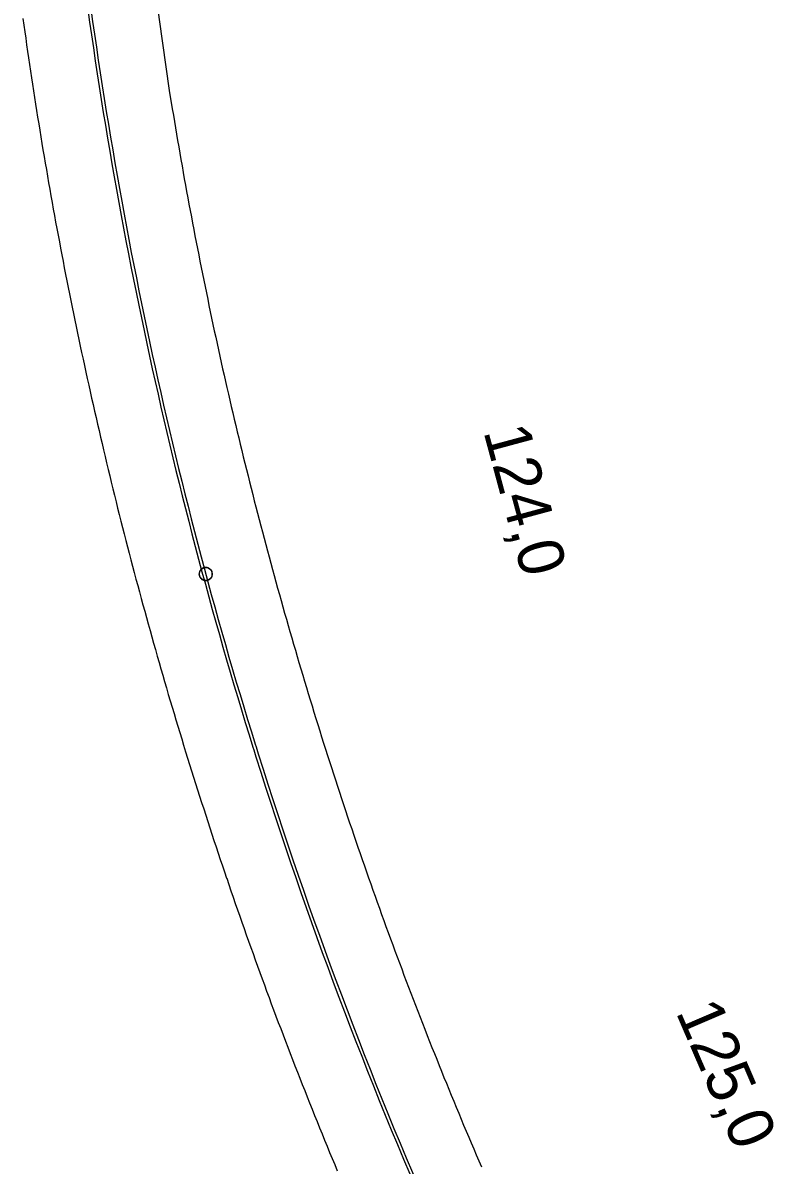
# Model space of a CAD drawing. Extents: x -670810 to -649614, y -1131928 to -1115069.
# Drawn here: x -670743 to -669596, y -1120256 to -1118513 of the extents above; entities that cross this region are included whole.
import ezdxf

# ---------------------------------------------------------------- set-up
doc = ezdxf.new("R2010")
doc.units = 0
for name, color, linetype in [('hranice_VRT_ZUR_Vysocina', 7, 'Continuous'), ('Situace - Osa koleje 2D', 7, 'Continuous'), ('Situace - Osa koleje tunel 2D', 7, 'Continuous'), ('Staničení - hlavní staničení + kolečka 1k', 7, 'Continuous')]:
    doc.layers.add(name, color=color, linetype=linetype)

# ---------------------------------------------------------------- blocks, each defined once
blk = doc.blocks.new('Sit10Kruh_101')
at = {"layer": 'Staničení - hlavní staničení + kolečka 1k'}
blk.add_lwpolyline([(10, 0), (9.98026, 0.6279), (9.92114, 1.25334), (9.82288, 1.87382), (9.68584, 2.4869), (9.51056, 3.09016), (9.29776, 3.68124), (9.04828, 4.2578), (8.76306, 4.81754), (8.44328, 5.35826), (8.09016, 5.87786), (7.70514, 6.37424), (7.28968, 6.84548), (6.84548, 7.28968), (6.37424, 7.70514), (5.87786, 8.09016), (5.35826, 8.44328), (4.81754, 8.76306), (4.2578, 9.04828), (3.68124, 9.29776), (3.09016, 9.51056), (2.4869, 9.68584), (1.87382, 9.82288), (1.25334, 9.92114), (0.6279, 9.98026), (0, 10), (-0.6279, 9.98026), (-1.25334, 9.92114), (-1.87382, 9.82288), (-2.4869, 9.68584), (-3.09016, 9.51056), (-3.68124, 9.29776), (-4.2578, 9.04828), (-4.81754, 8.76306), (-5.35826, 8.44328), (-5.87786, 8.09016), (-6.37424, 7.70514), (-6.84548, 7.28968), (-7.28968, 6.84548), (-7.70514, 6.37424), (-8.09016, 5.87786), (-8.44328, 5.35826), (-8.76306, 4.81754), (-9.04828, 4.2578), (-9.29776, 3.68124), (-9.51056, 3.09016), (-9.68584, 2.4869), (-9.82288, 1.87382), (-9.92114, 1.25334), (-9.98026, 0.6279), (-10, 0), (-9.98026, -0.6279), (-9.92114, -1.25334), (-9.82288, -1.87382), (-9.68584, -2.4869), (-9.51056, -3.09016), (-9.29776, -3.68124), (-9.04828, -4.2578), (-8.76306, -4.81754), (-8.44328, -5.35826), (-8.09016, -5.87786), (-7.70514, -6.37424), (-7.28968, -6.84548), (-6.84548, -7.28968), (-6.37424, -7.70514), (-5.87786, -8.09016), (-5.35826, -8.44328), (-4.81754, -8.76306), (-4.2578, -9.04828), (-3.68124, -9.29776), (-3.09016, -9.51056), (-2.4869, -9.68584), (-1.87382, -9.82288), (-1.25334, -9.92114), (-0.6279, -9.98026), (0, -10), (0.6279, -9.98026), (1.25334, -9.92114), (1.87382, -9.82288), (2.4869, -9.68584), (3.09016, -9.51056), (3.68124, -9.29776), (4.2578, -9.04828), (4.81754, -8.76306), (5.35826, -8.44328), (5.87786, -8.09016), (6.37424, -7.70514), (6.84548, -7.28968), (7.28968, -6.84548), (7.70514, -6.37424), (8.09016, -5.87786), (8.44328, -5.35826), (8.76306, -4.81754), (9.04828, -4.2578), (9.29776, -3.68124), (9.51056, -3.09016), (9.68584, -2.4869), (9.82288, -1.87382), (9.92114, -1.25334)], close=True, dxfattribs=at)
blk.add_circle((0, 0), 10, dxfattribs=at)

msp = doc.modelspace()

# ---------------------------------------------------------------- linework, layer by layer
at = {"layer": 'hranice_VRT_ZUR_Vysocina'}
for points in [[(-670742.9, -1118506.7), (-670741.5, -1118516.7), (-670740.1, -1118526.8), (-670738.6, -1118536.8), (-670737.2, -1118546.9), (-670735.8, -1118556.9), (-670734.3, -1118566.9), (-670732.8, -1118577), (-670731.3, -1118587), (-670729.8, -1118597.1), (-670728.3, -1118607.1), (-670726.7, -1118617.1), (-670725.2, -1118627.1), (-670723.6, -1118637.2), (-670722, -1118647.2), (-670720.4, -1118657.2), (-670718.8, -1118667.2), (-670717.2, -1118677.3), (-670715.5, -1118687.3), (-670713.9, -1118697.3), (-670712.2, -1118707.3), (-670710.5, -1118717.3), (-670708.8, -1118727.3), (-670707.1, -1118737.3), (-670705.4, -1118747.3), (-670703.6, -1118757.3), (-670701.9, -1118767.3), (-670700.1, -1118777.3), (-670698.3, -1118787.3), (-670696.5, -1118797.3), (-670694.7, -1118807.3), (-670692.9, -1118817.3), (-670691, -1118827.2), (-670689.2, -1118837.2), (-670687.3, -1118847.2), (-670685.4, -1118857.2), (-670683.5, -1118867.1), (-670681.6, -1118877.1), (-670679.7, -1118887.1), (-670677.7, -1118897), (-670675.8, -1118907), (-670673.8, -1118916.9), (-670671.8, -1118926.9), (-670669.8, -1118936.9), (-670667.8, -1118946.8), (-670665.8, -1118956.7), (-670663.7, -1118966.7), (-670661.7, -1118976.6), (-670659.6, -1118986.6), (-670657.5, -1118996.5), (-670655.4, -1119006.4), (-670653.3, -1119016.4), (-670651.2, -1119026.3), (-670649, -1119036.2), (-670646.9, -1119046.1), (-670644.7, -1119056), (-670642.5, -1119065.9), (-670640.3, -1119075.9), (-670638.1, -1119085.8), (-670635.9, -1119095.7), (-670633.6, -1119105.6), (-670631.4, -1119115.5), (-670629.1, -1119125.3), (-670626.8, -1119135.2), (-670624.5, -1119145.1), (-670622.2, -1119155), (-670619.9, -1119164.9), (-670617.6, -1119174.8), (-670615.2, -1119184.6), (-670612.9, -1119194.5), (-670610.5, -1119204.4), (-670608.1, -1119214.2), (-670605.7, -1119224.1), (-670603.2, -1119234), (-670600.8, -1119243.8), (-670598.4, -1119253.7), (-670595.9, -1119263.5), (-670593.4, -1119273.3), (-670590.9, -1119283.2), (-670588.4, -1119293), (-670585.9, -1119302.8), (-670583.3, -1119312.7), (-670580.8, -1119322.5), (-670578.2, -1119332.3), (-670575.7, -1119342.1), (-670573.1, -1119351.9), (-670570.5, -1119361.8), (-670567.8, -1119371.6), (-670565.2, -1119381.4), (-670562.6, -1119391.2), (-670559.9, -1119401), (-670557.2, -1119410.7), (-670554.5, -1119420.5), (-670551.8, -1119430.3), (-670549.1, -1119440.1), (-670546.4, -1119449.9), (-670543.6, -1119459.6), (-670540.9, -1119469.4), (-670538.1, -1119479.2), (-670535.3, -1119488.9), (-670532.5, -1119498.7), (-670529.7, -1119508.4), (-670526.9, -1119518.2), (-670524, -1119527.9), (-670521.2, -1119537.7), (-670518.3, -1119547.4), (-670515.4, -1119557.1), (-670512.5, -1119566.9), (-670509.6, -1119576.6), (-670506.7, -1119586.3), (-670503.7, -1119596), (-670500.8, -1119605.7), (-670497.8, -1119615.4), (-670494.8, -1119625.1), (-670491.8, -1119634.8), (-670488.8, -1119644.5), (-670485.8, -1119654.2), (-670482.7, -1119663.9), (-670479.7, -1119673.6), (-670476.6, -1119683.2), (-670473.5, -1119692.9), (-670470.4, -1119702.6), (-670467.3, -1119712.2), (-670464.2, -1119721.9), (-670461.1, -1119731.6), (-670457.9, -1119741.2), (-670454.8, -1119750.9), (-670451.6, -1119760.5), (-670448.4, -1119770.1), (-670445.2, -1119779.8), (-670442, -1119789.4), (-670438.8, -1119799), (-670435.5, -1119808.6), (-670432.3, -1119818.2), (-670432.2, -1119818.3), (-670429, -1119827.8), (-670425.7, -1119837.4), (-670422.4, -1119847), (-670419.1, -1119856.6), (-670415.8, -1119866.2), (-670412.4, -1119875.8), (-670409.1, -1119885.4), (-670405.7, -1119895), (-670402.3, -1119904.5), (-670398.9, -1119914.1), (-670395.5, -1119923.7), (-670392.1, -1119933.2), (-670388.6, -1119942.8), (-670385.2, -1119952.3), (-670381.7, -1119961.8), (-670378.3, -1119971.4), (-670374.8, -1119980.9), (-670371.3, -1119990.4), (-670367.7, -1120000), (-670364.2, -1120009.5), (-670360.7, -1120019), (-670357.1, -1120028.5), (-670353.5, -1120038), (-670349.9, -1120047.5), (-670346.3, -1120057), (-670342.7, -1120066.5), (-670339.1, -1120075.9), (-670335.5, -1120085.4), (-670331.8, -1120094.9), (-670328.1, -1120104.3), (-670324.5, -1120113.8), (-670320.8, -1120123.3), (-670317.1, -1120132.7), (-670313.3, -1120142.1), (-670309.6, -1120151.6), (-670305.9, -1120161), (-670302.1, -1120170.4), (-670298.3, -1120179.9), (-670294.5, -1120189.3), (-670290.7, -1120198.7), (-670286.9, -1120208.1), (-670283.1, -1120217.5), (-670279.2, -1120226.9), (-670275.4, -1120236.3), (-670271.5, -1120245.7), (-670267.6, -1120255), (-670263.7, -1120264.4)], [(-670519.7, -1118616.4), (-670515.1, -1118644.3), (-670513.5, -1118654), (-670511.9, -1118663.7), (-670510.3, -1118673.5), (-670508.7, -1118683.2), (-670507, -1118692.9), (-670505.4, -1118702.6), (-670503.7, -1118712.3), (-670502, -1118722), (-670500.3, -1118731.7), (-670498.6, -1118741.4), (-670496.8, -1118751.1), (-670495.1, -1118760.8), (-670493.3, -1118770.5), (-670491.5, -1118780.2), (-670489.7, -1118789.9), (-670487.9, -1118799.6), (-670486.1, -1118809.3), (-670484.3, -1118819), (-670482.4, -1118828.7), (-670480.6, -1118838.4), (-670478.7, -1118848), (-670476.8, -1118857.7), (-670474.9, -1118867.4), (-670473, -1118877.1), (-670471.1, -1118886.7), (-670469.1, -1118896.4), (-670467.2, -1118906.1), (-670465.2, -1118915.7), (-670463.2, -1118925.4), (-670461.2, -1118935), (-670459.2, -1118944.7), (-670457.2, -1118954.3), (-670455.2, -1118964), (-670453.1, -1118973.6), (-670451.1, -1118983.2), (-670449, -1118992.9), (-670446.9, -1119002.5), (-670444.8, -1119012.1), (-670442.7, -1119021.8), (-670440.5, -1119031.4), (-670438.4, -1119041), (-670436.2, -1119050.6), (-670434, -1119060.2), (-670431.8, -1119069.8), (-670429.6, -1119079.5), (-670427.4, -1119089.1), (-670425.2, -1119098.7), (-670422.9, -1119108.3), (-670420.7, -1119117.9), (-670418.4, -1119127.4), (-670416.1, -1119137), (-670413.8, -1119146.6), (-670411.5, -1119156.2), (-670409.2, -1119165.8), (-670406.9, -1119175.4), (-670404.5, -1119184.9), (-670402.1, -1119194.5), (-670399.7, -1119204.1), (-670397.4, -1119213.6), (-670394.9, -1119223.2), (-670392.5, -1119232.7), (-670390.1, -1119242.3), (-670387.6, -1119251.8), (-670385.2, -1119261.4), (-670382.7, -1119270.9), (-670380.2, -1119280.5), (-670377.7, -1119290), (-670375.2, -1119299.5), (-670372.7, -1119309), (-670370.1, -1119318.6), (-670367.6, -1119328.1), (-670365, -1119337.6), (-670362.4, -1119347.1), (-670359.8, -1119356.6), (-670357.2, -1119366.1), (-670354.6, -1119375.6), (-670351.9, -1119385.1), (-670349.3, -1119394.6), (-670346.6, -1119404.1), (-670343.9, -1119413.6), (-670341.2, -1119423.1), (-670338.5, -1119432.6), (-670335.8, -1119442), (-670333.1, -1119451.5), (-670330.3, -1119461), (-670327.5, -1119470.4), (-670324.8, -1119479.9), (-670322, -1119489.3), (-670319.2, -1119498.8), (-670316.4, -1119508.2), (-670313.5, -1119517.7), (-670310.7, -1119527.1), (-670307.8, -1119536.6), (-670305, -1119546), (-670302.1, -1119555.4), (-670299.2, -1119564.8), (-670296.3, -1119574.3), (-670293.4, -1119583.7), (-670290.4, -1119593.1), (-670287.5, -1119602.5), (-670284.5, -1119611.9), (-670281.5, -1119621.3), (-670278.5, -1119630.7), (-670275.5, -1119640.1), (-670272.5, -1119649.4), (-670269.5, -1119658.8), (-670266.4, -1119668.2), (-670263.4, -1119677.6), (-670260.3, -1119686.9), (-670257.2, -1119696.3), (-670254.1, -1119705.7), (-670251, -1119715), (-670247.9, -1119724.4), (-670244.8, -1119733.7), (-670241.6, -1119743), (-670238.4, -1119752.4), (-670235.3, -1119761.7), (-670232.1, -1119771), (-670228.9, -1119780.4), (-670225.6, -1119789.7), (-670222.4, -1119799), (-670219.2, -1119808.3), (-670215.9, -1119817.6), (-670212.6, -1119826.9), (-670209.4, -1119836.2), (-670206.1, -1119845.5), (-670202.7, -1119854.8), (-670199.4, -1119864), (-670196.1, -1119873.3), (-670192.7, -1119882.6), (-670189.4, -1119891.8), (-670186, -1119901.1), (-670182.6, -1119910.4), (-670179.2, -1119919.6), (-670175.8, -1119928.9), (-670172.4, -1119938.1), (-670168.9, -1119947.3), (-670165.5, -1119956.6), (-670162, -1119965.8), (-670158.5, -1119975), (-670155, -1119984.2), (-670151.5, -1119993.4), (-670148, -1120002.7), (-670144.4, -1120011.9), (-670140.9, -1120021.1), (-670137.3, -1120030.2), (-670133.8, -1120039.4), (-670130.2, -1120048.6), (-670126.6, -1120057.8), (-670122.9, -1120067), (-670119.3, -1120076.1), (-670115.7, -1120085.3), (-670112, -1120094.4), (-670108.4, -1120103.6), (-670104.7, -1120112.7), (-670101, -1120121.9), (-670097.3, -1120131), (-670093.6, -1120140.1), (-670089.8, -1120149.3), (-670086.1, -1120158.4), (-670082.3, -1120167.5), (-670078.6, -1120176.6), (-670074.8, -1120185.7), (-670071, -1120194.8), (-670067.2, -1120203.9), (-670063.3, -1120213), (-670059.5, -1120222), (-670055.7, -1120231.1), (-670051.8, -1120240.2), (-670047.9, -1120249.3), (-670044, -1120258.3)]]:
    msp.add_lwpolyline(points, dxfattribs=at)
msp.add_arc((-663695.1, -1117599), 6900, 169.21643, 188.47877, dxfattribs=at)
at = {"layer": 'Situace - Osa koleje 2D'}
for radius, start, end in [(7004.7, 186.8992, 197.32601), (7000, 186.8992, 197.29879), (7000, 197.42407, 203.79122), (7004.7, 197.45116, 203.79126)]:
    msp.add_arc((-663705.3, -1117532.4), radius, start, end, dxfattribs=at)
at = {"layer": 'Situace - Osa koleje tunel 2D'}
for radius, start, end in [(7004.7, 197.32601, 197.45116), (7000, 197.29879, 197.42407)]:
    msp.add_arc((-663705.3, -1117532.4), radius, start, end, dxfattribs=at)

# ---------------------------------------------------------------- block references
at = {"layer": 'Staničení - hlavní staničení + kolečka 1k', "rotation": -74.91568799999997}
msp.add_blockref('Sit10Kruh_101', (-670464.1, -1119354.1), dxfattribs=at)

# ---------------------------------------------------------------- texts
at = {"layer": 'Staničení - hlavní staničení + kolečka 1k'}
for s, rotation, p in [('124,0', 285.0843, (-670041.2, -1119136.3)), ('125,0', 293.2694, (-669748.3, -1120022))]:
    msp.add_text(s, height=70, rotation=rotation, dxfattribs=at).set_placement(p)

doc.saveas('drawing.dxf')
